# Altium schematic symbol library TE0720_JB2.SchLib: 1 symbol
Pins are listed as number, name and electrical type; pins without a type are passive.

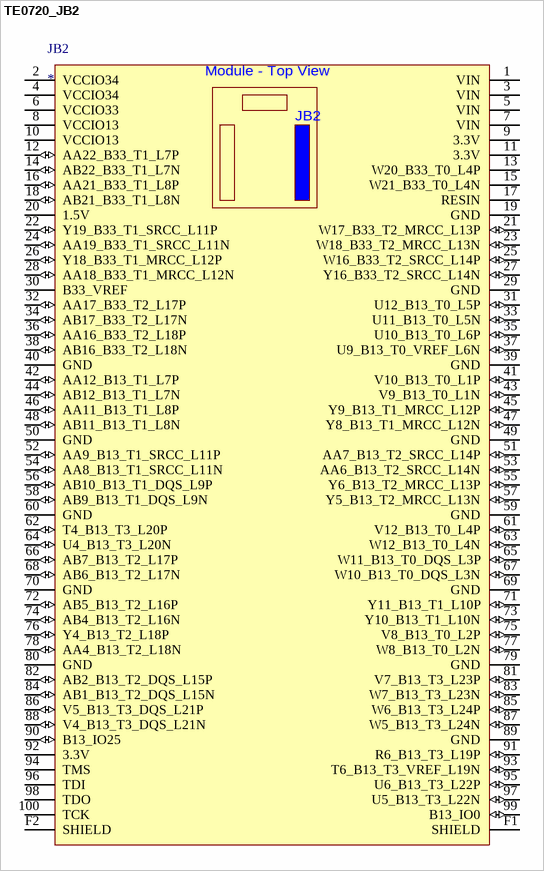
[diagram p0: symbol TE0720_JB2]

## TE0720_JB2
designator JB2
pins: 1 VIN (power), 2 VCCIO34 (power), 3 VIN (power), 4 VCCIO34 (power), 5 VIN (power), 6 VCCIO33 (power), 7 VIN (power), 8 VCCIO13 (power), 9 3.3V (power), 10 VCCIO13 (power), 11 3.3V (power), 12 AA22_B33_T1_L7P (io), 13 W20_B33_T0_L4P, 14 AB22_B33_T1_L7N (io), 15 W21_B33_T0_L4N, 16 AA21_B33_T1_L8P (io), 17 RESIN, 18 AB21_B33_T1_L8N (io), 19 GND (power), 20 1.5V (power), 21 W17_B33_T2_MRCC_L13P (io), 22 Y19_B33_T1_SRCC_L11P (io), 23 W18_B33_T2_MRCC_L13N (io), 24 AA19_B33_T1_SRCC_L11N (io), 25 W16_B33_T2_SRCC_L14P (io), 26 Y18_B33_T1_MRCC_L12P (io), 27 Y16_B33_T2_SRCC_L14N (io), 28 AA18_B33_T1_MRCC_L12N (io), 29 GND (power), 30 B33_VREF (power), 31 U12_B13_T0_L5P (io), 32 AA17_B33_T2_L17P (io), 33 U11_B13_T0_L5N (io), 34 AB17_B33_T2_L17N (io), 35 U10_B13_T0_L6P (io), 36 AA16_B33_T2_L18P (io), 37 U9_B13_T0_VREF_L6N (io), 38 AB16_B33_T2_L18N (io), 39 GND (power), 40 GND (power), 41 V10_B13_T0_L1P (io), 42 AA12_B13_T1_L7P (io), 43 V9_B13_T0_L1N (io), 44 AB12_B13_T1_L7N (io), 45 Y9_B13_T1_MRCC_L12P (io), 46 AA11_B13_T1_L8P (io), 47 Y8_B13_T1_MRCC_L12N (io), 48 AB11_B13_T1_L8N (io), 49 GND (power), 50 GND (power), 51 AA7_B13_T2_SRCC_L14P (io), 52 AA9_B13_T1_SRCC_L11P (io), 53 AA6_B13_T2_SRCC_L14N (io), 54 AA8_B13_T1_SRCC_L11N (io), 55 Y6_B13_T2_MRCC_L13P (io), 56 AB10_B13_T1_DQS_L9P (io), 57 Y5_B13_T2_MRCC_L13N (io), 58 AB9_B13_T1_DQS_L9N (io), 59 GND (power), 60 GND (power), 61 V12_B13_T0_L4P (io), 62 T4_B13_T3_L20P (io), 63 W12_B13_T0_L4N (io), 64 U4_B13_T3_L20N (io), 65 W11_B13_T0_DQS_L3P (io), 66 AB7_B13_T2_L17P (io), 67 W10_B13_T0_DQS_L3N (io), 68 AB6_B13_T2_L17N (io), 69 GND (power), 70 GND (power), 71 Y11_B13_T1_L10P (io), 72 AB5_B13_T2_L16P (io), 73 Y10_B13_T1_L10N (io), 74 AB4_B13_T2_L16N (io), 75 V8_B13_T0_L2P (io), 76 Y4_B13_T2_L18P (io), 77 W8_B13_T0_L2N (io), 78 AA4_B13_T2_L18N (io), 79 GND (power), 80 GND (power), 81 V7_B13_T3_L23P (io), 82 AB2_B13_T2_DQS_L15P (io), 83 W7_B13_T3_L23N (io), 84 AB1_B13_T2_DQS_L15N (io), 85 W6_B13_T3_L24P (io), 86 V5_B13_T3_DQS_L21P (io), 87 W5_B13_T3_L24N (io), 88 V4_B13_T3_DQS_L21N (io), 89 GND (power), 90 B13_IO25 (io), 91 R6_B13_T3_L19P (io), 92 3.3V (power), 93 T6_B13_T3_VREF_L19N (io), 94 TMS, 95 U6_B13_T3_L22P (io), 96 TDI, 97 U5_B13_T3_L22N (io), 98 TDO, 99 B13_IO0 (io), 100 TCK, F1 SHIELD (power), F2 SHIELD (power)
